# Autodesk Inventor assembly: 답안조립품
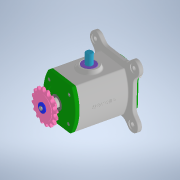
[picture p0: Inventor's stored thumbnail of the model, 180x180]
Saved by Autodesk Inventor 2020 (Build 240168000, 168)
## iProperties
Created: 2022-01
Part Number: 답안조립품
Document SubType Name: Assembly
Designer: user
Author: user
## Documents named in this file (13)
- C:\Users\user\Desktop\오목눈이\답안조립품.iam
- C:\Users\user\Desktop\720117V1013\베어링 6203.ipt
- C:\Users\user\Desktop\오목눈이\본체.ipt
- C:\Users\user\Desktop\720117V1013\볼트 M4 x 12.ipt
- C:\Users\user\Desktop\720117V1013\부시.ipt
- C:\Users\user\Desktop\720117V1013\스프로킷.ipt
- C:\Users\user\Desktop\720117V1013\슬라이더.ipt
- C:\Users\user\Desktop\720117V1013\오일 실 17 x 30 x 8.ipt
- C:\Users\user\Desktop\720117V1013\와셔 4 x 20.ipt
- C:\Users\user\Desktop\720117V1013\육각머리볼트 M4.ipt
- C:\Users\user\Desktop\720117V1013\커버.ipt
- C:\Users\user\Desktop\720117V1013\키 5 x 5.ipt
- C:\Users\user\Desktop\720117V1013\편심축.ipt
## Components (8 placed, 1 different names)
1. M4x0.7x12:1
2. M4x0.7x12:3
3. M4x0.7x12:4
4. M4x0.7x12:5
5. M4x0.7x12:2
6. M4x0.7x12:6
7. M4x0.7x12:7
8. M4x0.7x12:8
